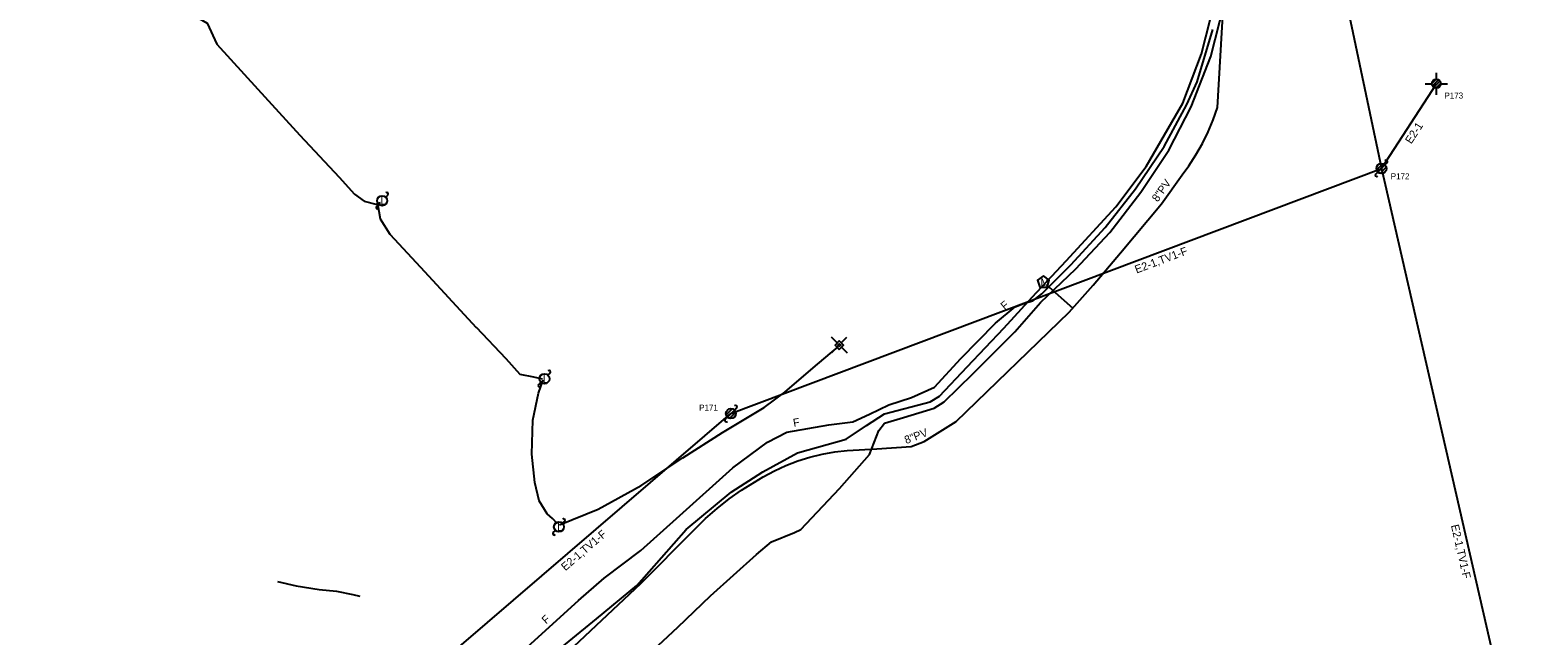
# Model space of a CAD drawing. Extents: x 1741604 to 1825760, y 1164229 to 1194908.
# Drawn here: x 1771575 to 1772322, y 1178956 to 1179258 of the extents above; entities that cross this region are included whole.
import ezdxf

# ---------------------------------------------------------------- set-up
doc = ezdxf.new("R2010")
doc.units = 0
for name, color, linetype in [('RD_EX_SU_Elec', 7, 'Continuous'), ('RD_EX_SU_H2O', 7, 'Continuous'), ('RD_EX_SU_Ovhd', 7, 'Continuous'), ('RD_EX_SU_Pole', 7, 'Continuous'), ('RD_EX_SU_Telecom', 7, 'Continuous'), ('RD_EX_SU_TX_H2O', 7, 'Continuous'), ('RD_EX_SU_TX_Pole', 7, 'Continuous'), ('RD_EX_SU_TX_Telecom', 7, 'Continuous')]:
    doc.layers.add(name, color=color, linetype=linetype)

# ---------------------------------------------------------------- blocks, each defined once
blk = doc.blocks.new('SUE_WM')
at = {"layer": 'RD_EX_SU_H2O'}
blk.add_lwpolyline([(0, 3.05), (-2.9, 0.94), (-1.79, -2.47), (1.79, -2.47), (2.9, 0.94)], close=True, dxfattribs=at)
blk.add_text('M', height=3.75, dxfattribs=at).set_placement((-1.43, -1.88))
blk = doc.blocks.new('SUE_PGP')
at = {"layer": 'RD_EX_SU_Pole'}
for p, q in [((-1.06, 1.06), (-3.89, 3.89)), ((1.02, 1.12), (3.86, 3.96)), ((-1.11, -1.04), (-3.94, -3.87)), ((1.06, -1.06), (3.89, -3.89))]:
    blk.add_line(p, q, dxfattribs=at)
for points in [[(0, -2.12), (2.12, 0), (0, 2.12), (-2.12, 0)], [(0, -0.71), (0.71, 0), (0, 0.71), (-0.71, 0)]]:
    blk.add_lwpolyline(points, close=True, dxfattribs=at)

msp = doc.modelspace()

# ---------------------------------------------------------------- linework, layer by layer
at = {"layer": 'RD_EX_SU_Elec'}
for points in [[(1771574.77, 1179352.66), (1771576.54, 1179349.44), (1771580.78, 1179345.73), (1771590.55, 1179334.31), (1771601.2, 1179322.13), (1771639.52, 1179282.96), (1771654.13, 1179267.02), (1771663.36, 1179261.68), (1771668.21, 1179251.18), (1771688.65, 1179228.66), (1771709.75, 1179205.57), (1771729.34, 1179184.53), (1771736.98, 1179176.12), (1771741.79, 1179172.64), (1771747.65, 1179171.13), (1771749.97, 1179171.94)], [(1771748.42, 1179171.4), (1771749.82, 1179163.77), (1771754.65, 1179156.15), (1771769.92, 1179139.6), (1771797.88, 1179109.46)], [(1771797.85, 1179109.65), (1771812.62, 1179093.9), (1771819.69, 1179086.08), (1771826.41, 1179084.68), (1771830.8, 1179083.8)], [(1771839.47, 1179010.78), (1771858.77, 1179018.62), (1771880.3, 1179030.33), (1771901.1, 1179044.23), (1771920.86, 1179056.95), (1771941.71, 1179069.33), (1771952.16, 1179077), (1771966.24, 1179089.31), (1771974.72, 1179096.45), (1771978.71, 1179099.67)], [(1771838.38, 1179011.26), (1771835.93, 1179013.91), (1771833.27, 1179016.16), (1771829.26, 1179022.65), (1771827.15, 1179031.92), (1771825.62, 1179046.12), (1771826.19, 1179063.15), (1771828.92, 1179076.65), (1771831.27, 1179083.27)], [(1771698.57, 1178982.37), (1771707.87, 1178980.19), (1771719.28, 1178978.35), (1771728.04, 1178977.53), (1771736.12, 1178975.89), (1771739.74, 1178975.11)]]:
    msp.add_lwpolyline(points, dxfattribs=at)
at = {"layer": 'RD_EX_SU_H2O'}
msp.add_line((1772082.65, 1179130.89), (1772095.94, 1179119.08), dxfattribs=at)
for points in [[(1772037.75, 1179062.48), (1772094.13, 1179117.04), (1772106.13, 1179130.54), (1772119.91, 1179146.76), (1772140.38, 1179171.22), (1772150.65, 1179185.78), (1772153.95, 1179190.3), (1772157.52, 1179195.79), (1772160.75, 1179201.47), (1772163.65, 1179207.33), (1772166.19, 1179213.36), (1772168.38, 1179219.52), (1772178.89, 1179400.48), (1772274.66, 1179556.01)], [(1771818.84, 1178923.65), (1771880.14, 1178981.38), (1771906.41, 1179007.91), (1771907.05, 1179008.58), (1771912.5, 1179013.89), (1771918.25, 1179018.93), (1771924.26, 1179023.65), (1771930.5, 1179028.06), (1771936.91, 1179032.09), (1771941.27, 1179034.78), (1771946.84, 1179037.8), (1771952.61, 1179040.45), (1771958.54, 1179042.73), (1771964.6, 1179044.63), (1771970.76, 1179046.13), (1771977.02, 1179047.24), (1771983.31, 1179047.94), (1771998.07, 1179048.76), (1772015.3, 1179049.91), (1772021.8, 1179052.41), (1772037.75, 1179062.48)]]:
    msp.add_lwpolyline(points, dxfattribs=at)
at = {"layer": 'RD_EX_SU_Ovhd'}
for p, q in [((1772188.69, 1179482.56), (1772250.24, 1179188.93)), ((1772250.24, 1179188.93), (1772277.69, 1179231.35)), ((1771925.15, 1179066.37), (1772250.24, 1179188.93)), ((1772250.24, 1179188.93), (1772321.56, 1178877.46)), ((1771732.23, 1178900.83), (1771925.15, 1179066.37))]:
    msp.add_line(p, q, dxfattribs=at)
at = {"layer": 'RD_EX_SU_Pole'}
for p, q in [((1772272.16, 1179231.35), (1772275.47, 1179231.35)), ((1772275.47, 1179231.48), (1772277.56, 1179233.56)), ((1772275.72, 1179230.32), (1772278.72, 1179233.31)), ((1772276.38, 1179229.56), (1772279.48, 1179232.65)), ((1772277.38, 1179229.15), (1772279.88, 1179231.64)), ((1772277.69, 1179233.56), (1772277.69, 1179236.87)), ((1772279.9, 1179231.35), (1772283.21, 1179231.35)), ((1772277.69, 1179225.82), (1772277.69, 1179229.13)), ((1772247.41, 1179186.11), (1772248.47, 1179187.17)), ((1772247.82, 1179188.29), (1772250.89, 1179191.35)), ((1772248.47, 1179187.17), (1772252.01, 1179190.7)), ((1772249.59, 1179186.52), (1772252.65, 1179189.58)), ((1772252.01, 1179190.7), (1772253.07, 1179191.76)), ((1771752.62, 1179174.61), (1771753.68, 1179175.67)), ((1771748.02, 1179170.01), (1771749.08, 1179171.07)), ((1771829.09, 1179080.95), (1771830.15, 1179082.01)), ((1771833.69, 1179085.55), (1771834.75, 1179086.61)), ((1771922.73, 1179065.72), (1771925.79, 1179068.79)), ((1771923.38, 1179064.6), (1771926.91, 1179068.14)), ((1771924.5, 1179063.96), (1771927.56, 1179067.02)), ((1771926.91, 1179068.14), (1771927.97, 1179069.2)), ((1771922.32, 1179063.54), (1771923.38, 1179064.6)), ((1771836.37, 1179006.89), (1771837.44, 1179007.95)), ((1771840.97, 1179011.49), (1771842.03, 1179012.55))]:
    msp.add_line(p, q, dxfattribs=at)
for centre, radius in [((1772277.69, 1179231.35), 2.22), ((1772250.24, 1179188.93), 2.5), ((1771750.85, 1179172.84), 2.5), ((1771831.92, 1179083.78), 2.5), ((1771925.15, 1179066.37), 2.5), ((1771839.2, 1179009.72), 2.5)]:
    msp.add_circle(centre, radius, dxfattribs=at)
for centre, start, end in [((1772252.54, 1179192.29), 315, 135), ((1772247.94, 1179185.57), 135, 315), ((1771753.15, 1179176.2), 315, 135), ((1771748.55, 1179169.48), 135, 315), ((1771834.22, 1179087.14), 315, 135), ((1771829.62, 1179080.42), 135, 315), ((1771927.44, 1179069.73), 315, 135), ((1771922.85, 1179063.01), 135, 315), ((1771841.5, 1179013.08), 315, 135), ((1771836.9, 1179006.36), 135, 315)]:
    msp.add_arc(centre, 0.75, start, end, dxfattribs=at)
at = {"layer": 'RD_EX_SU_Telecom'}
for points in [[(1771828.76, 1178939.84), (1771857.91, 1178963.65), (1771878.06, 1178980.38), (1771902.74, 1179008.45), (1771925.28, 1179027.11), (1771941.03, 1179037.28), (1771958.34, 1179046.79), (1771982.7, 1179053.63), (1771992.87, 1179060.36), (1772001.83, 1179066.26), (1772024.72, 1179072.25), (1772029.37, 1179075.04), (1772043.25, 1179089.69), (1772061.48, 1179109.04), (1772075.72, 1179124.61), (1772092.73, 1179142.81), (1772117.55, 1179169.8), (1772132.64, 1179189.95), (1772151.05, 1179221.54), (1772160.3, 1179246.23), (1772166.83, 1179271.88)], [(1771854.72, 1178918.75), (1771898.53, 1178959.51), (1771914.97, 1178975.23), (1771937.95, 1178995.84), (1771945.39, 1179002.14), (1771956.93, 1179006.9), (1771960.16, 1179008.43), (1771979.38, 1179028.89), (1771994.47, 1179045.85), (1771999.07, 1179057.89), (1772001.87, 1179061.49), (1772011.34, 1179064.44), (1772026.73, 1179069.13), (1772031.73, 1179072.17), (1772046.09, 1179086.24), (1772067.1, 1179107.28), (1772079.8, 1179121.97), (1772097.6, 1179138.7), (1772114.45, 1179157.01), (1772130.06, 1179177.09), (1772144, 1179198.08), (1772155.14, 1179219.73), (1772164.98, 1179244.95), (1772171.66, 1179271.2)], [(1771821.63, 1178948.07), (1771848.97, 1178972.89), (1771861.85, 1178984.08), (1771880.12, 1178997.82), (1771897.96, 1179013.87), (1771926.07, 1179039.21), (1771943.38, 1179052.08), (1771953.16, 1179057.05), (1771974.1, 1179060.81), (1771986.04, 1179062.16), (1771994.38, 1179066.08), (1772004.02, 1179070.69), (1772015.43, 1179074.37), (1772026.84, 1179079.62), (1772039.98, 1179093.83), (1772057.4, 1179111.61), (1772067.13, 1179119.68), (1772072.38, 1179121.78), (1772075.98, 1179122.68), (1772080.58, 1179126.33), (1772094.99, 1179140.76), (1772112.25, 1179159.39), (1772127.38, 1179178.85), (1772141.66, 1179199.9), (1772152.97, 1179220.87), (1772158.21, 1179232.3), (1772165.96, 1179258.54)]]:
    msp.add_lwpolyline(points, dxfattribs=at)

# ---------------------------------------------------------------- block references
at = {"layer": 'RD_EX_SU_H2O'}
msp.add_blockref('SUE_WM', (1772081.33, 1179132.13), dxfattribs=at)
at = {"layer": 'RD_EX_SU_Pole'}
msp.add_blockref('SUE_PGP', (1771979.28, 1179100.61), dxfattribs=at)

# ---------------------------------------------------------------- texts
at = {"layer": 'RD_EX_SU_Ovhd'}
for s, rotation, p in [('E2-1', 57.09101, (1772265.15, 1179200.93)), ('E2-1,TV1-F', 20.65679, (1772127.88, 1179136.39)), ('E2-1,TV1-F', 40.63277, (1771842.39, 1178987.48)), ('E2-1,TV1-F', 282.8978, (1772284.96, 1179010.42))]:
    msp.add_text(s, height=4, rotation=rotation, dxfattribs=at).set_placement(p)
at = {"layer": 'RD_EX_SU_Pole'}
for p in [(1771749.99, 1179170.84), (1771831.06, 1179081.78), (1771838.34, 1179007.72)]:
    msp.add_text('L', height=4, dxfattribs=at).set_placement(p)
at = {"layer": 'RD_EX_SU_TX_H2O'}
for rotation, p in [(54.81895, (1772138.44, 1179171.93)), (21.04514, (1772012.75, 1179051.07))]:
    msp.add_text('8"PV', height=4, rotation=rotation, dxfattribs=at).set_placement(p)
at = {"layer": 'RD_EX_SU_TX_Pole'}
for s, p in [('P173', (1772281.73, 1179223.94)), ('P172', (1772254.91, 1179183.56)), ('P171', (1771909.26, 1179067.85))]:
    msp.add_text(s, height=3, dxfattribs=at).set_placement(p)
at = {"layer": 'RD_EX_SU_TX_Telecom'}
for rotation, p in [(39.66902, (1772061.96, 1179117.99)), (10.19045, (1771956.57, 1179059.69)), (42.22985, (1771832.76, 1178960.87))]:
    msp.add_text('F', height=4, rotation=rotation, dxfattribs=at).set_placement(p)

doc.saveas('drawing.dxf')
